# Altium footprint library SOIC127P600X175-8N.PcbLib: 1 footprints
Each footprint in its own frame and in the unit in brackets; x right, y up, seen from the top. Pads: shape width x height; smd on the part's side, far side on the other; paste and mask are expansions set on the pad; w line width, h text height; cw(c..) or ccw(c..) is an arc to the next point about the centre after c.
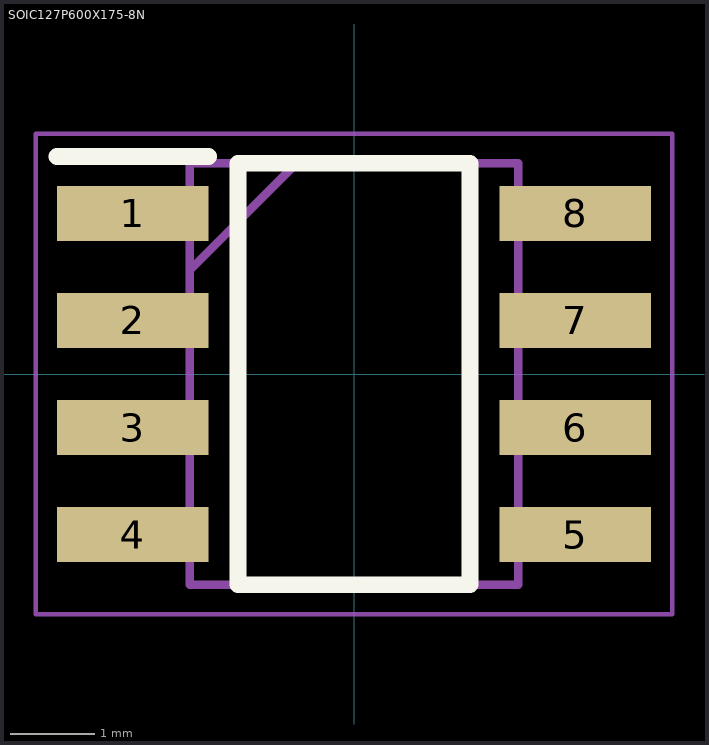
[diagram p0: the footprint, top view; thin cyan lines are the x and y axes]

## SOIC127P600X175-8N [mm]
pads (8):
  rect 1.8x0.65 smd: 1(-2.625,1.905) 2(-2.625,0.635) 3(-2.625,-0.635) 4(-2.625,-1.905) 5(2.625,-1.905) 6(2.625,-0.635) 7(2.625,0.635) 8(2.625,1.905)
Top Overlay:
  lines w0.2: -3.525,2.58 -1.725,2.58 ; -1.375,-2.5 1.375,-2.5 1.375,2.5 -1.375,2.5 -1.375,-2.5
Mechanical 15:
  lines w0.1: -1.95,1.23 -0.68,2.5 ; -1.95,-2.5 1.95,-2.5 1.95,2.5 -1.95,2.5 -1.95,-2.5
Mechanical 20:
  lines w0.05: -3.775,-2.85 3.775,-2.85 3.775,2.85 -3.775,2.85 -3.775,-2.85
